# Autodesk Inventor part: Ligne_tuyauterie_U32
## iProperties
Shininess: 64.0
Length Units: 11269
Angle Units: 11279
Time Units: 11290
Mass Units: 11283
Length Display Precision: 3
Angle Display Precision: 2
Compacted: True
Part Number: Ligne_tuyauterie_U32
Document SubType Name: Modeling
Created: 2008-06
Material: Par défaut
Designer: plup
Density: 0.0
Volumn: 0.0
Area: 0.0
PropertySet Name: Model Information
Control State: 0
Master: False
Checked Out: False
DESIGNATION: pièce
Author: plup
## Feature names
1. Balayage1
2. Balayage2
